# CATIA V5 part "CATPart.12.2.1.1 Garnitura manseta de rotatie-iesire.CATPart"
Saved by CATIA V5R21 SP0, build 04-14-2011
Part number: Garnitura manseta de rotatie.4
Bounding box of the stored display mesh (mm): x 1.667 to 11.667, y -30.959 to 30.959, z -30.959 to 30.959
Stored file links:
  C:\Users\MIRCEA\Desktop\MOM\Mogan\model\CATPart.12.2.1.1 Garnitura manseta de rotatie-iesire.CATPart
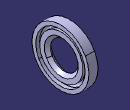
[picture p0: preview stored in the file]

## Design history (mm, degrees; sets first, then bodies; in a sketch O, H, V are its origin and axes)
Parameters
  d = 35 mm
  D = 62 mm
  h = 10 mm
Body1 (main body)
  Sketch1 on xy-plane, origin (0, 0, 0), H (1, 0, 0), V (0, 1, 0)
    point P1 (1.6667, 31)
    line L1 (1.6667, 31) -> (11.6667, 31)
    point P2 (11.6667, 31)
    line L2 (11.6667, 31) -> (11.6667, 26.9167)
    line L3 (11.6667, 26.9167) -> (7.5301, 26.9167)
    arc A1 centre (5.6667, 25.25) radius 2.5 from (7.5301, 26.9167) to (7.5301, 23.5833) ccw
    point P5 (5.6667, 25.25)
    point P6 (7.5301, 26.9167)
    line L4 (7.5301, 23.5833) -> (10.6667, 23.5833)
    point P9 (1.6667, 31)
    point P10 (11.6667, 31)
    point P11 (11.6667, 31)
    line L5 (10.6667, 23.5833) -> (10.6667, 18.5)
    point P12 (10.6667, 18.5)
    line L6 (10.6667, 18.5) -> (7.3333, 15.1667)
    point P13 (7.3333, 15.1667)
    line L7 (7.3333, 15.1667) -> (1.6667, 20.8333)
    line L8 (1.6667, 20.8333) -> (1.6667, 31)
    distance P1 H = 31 {= D /2}
    radius A1 = 2.5 {= h/4}
    distance P1 P2 = 10 {= h}
    angle L6 H = 135
    distance P12 H = 18.5 {= d /2+1 mm}
    distance P5 H = 25.25 {= (D+d)/4+ 1mm}
    distance L4 H = 23.5833 {= Sketch1.distance(P5 H) - Sketch1.radius(A1) /1.5}
    distance L3 H = 26.9167 {= Sketch1.distance(P5 H) +Sketch1.radius(A1) /1.5}
    distance P13 L5 = 3.3333 {= h/3}
    distance P5 L8 = 4 {= h/2.5}
    distance L5 L2 = 1
    horizontal: L1 H, L3 H, L4 H
    vertical: L2 V, L5 V, L8 V
    coincidence: A1 P6, P6 L3, L1 P1, L1 P2, L2 P2, P11 P2, P10 P2, P9 P1
    perpendicularity: L7 L6
  Shaft1: profile Sketch1, axis Sketch1.H, angle 360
